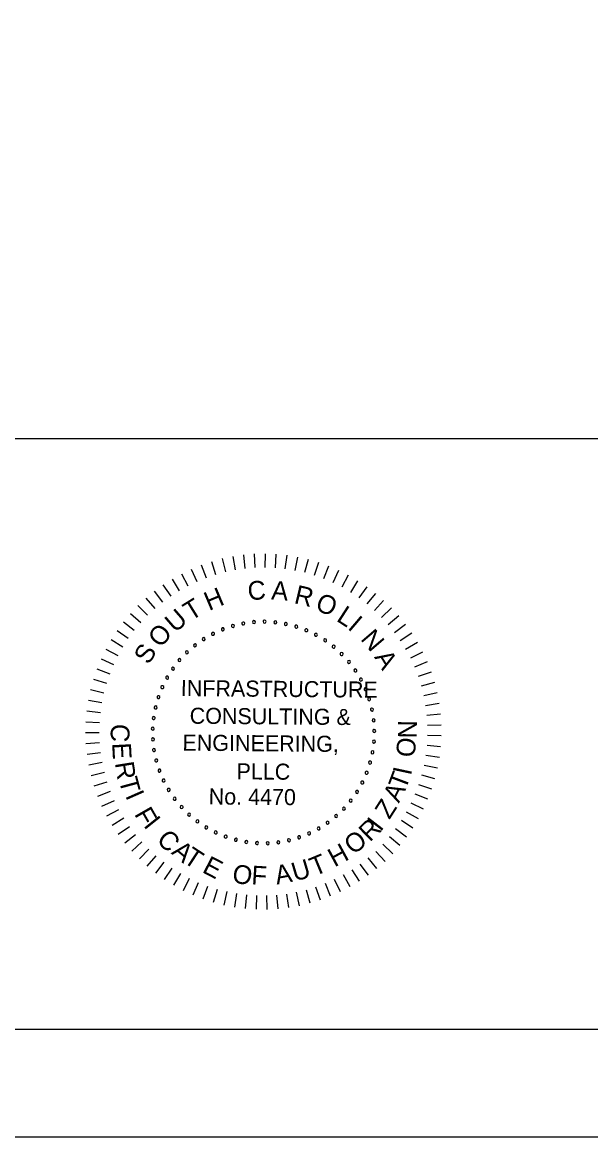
# Model space of a CAD drawing. Extents: x -121.2 to -24.9, y 6.4 to 66.6.
# Drawn here: x -53.93 to -46.88, y 6.35 to 20.18 of the extents above; entities that cross this region are included whole.
import ezdxf

# ---------------------------------------------------------------- set-up
doc = ezdxf.new("R2010")
doc.units = 0
for name, color, linetype in [('BR_BORDER LINES', 7, 'Continuous'), ('BR_TEXT', 7, 'Continuous'), ('Level 31', 7, 'Continuous')]:
    doc.layers.add(name, color=color, linetype=linetype)

msp = doc.modelspace()

# ---------------------------------------------------------------- linework, layer by layer
at = {"layer": 'BR_BORDER LINES'}
for p, q in [((-60.804, 15.017), (-46.496, 15.017)), ((-116.272, 7.683), (-26.496, 7.683))]:
    msp.add_line(p, q, dxfattribs=at)
at = {"layer": 'BR_TEXT'}
for p, q in [((-51.188, 13.572), (-51.169, 13.403)), ((-51.054, 13.583), (-51.045, 13.413)), ((-50.919, 13.586), (-50.921, 13.416)), ((-50.785, 13.58), (-50.796, 13.411)), ((-50.651, 13.567), (-50.673, 13.399)), ((-51.711, 13.447), (-51.651, 13.288)), ((-51.583, 13.49), (-51.533, 13.328)), ((-51.453, 13.526), (-51.413, 13.36)), ((-51.321, 13.553), (-51.292, 13.386)), ((-50.518, 13.545), (-50.55, 13.378)), ((-50.387, 13.515), (-50.429, 13.351)), ((-50.257, 13.478), (-50.31, 13.316)), ((-50.131, 13.432), (-50.193, 13.274)), ((-51.957, 13.338), (-51.878, 13.187)), ((-51.835, 13.396), (-51.766, 13.241)), ((-50.007, 13.379), (-50.079, 13.225)), ((-49.887, 13.318), (-49.968, 13.169)), ((-52.187, 13.2), (-52.091, 13.06)), ((-52.074, 13.272), (-51.987, 13.127)), ((-49.771, 13.251), (-49.86, 13.106)), ((-49.659, 13.176), (-49.757, 13.037)), ((-52.4, 13.034), (-52.287, 12.907)), ((-52.296, 13.12), (-52.192, 12.986)), ((-49.551, 13.094), (-49.658, 12.962)), ((-49.449, 13.006), (-49.564, 12.881)), ((-52.498, 12.942), (-52.378, 12.822)), ((-49.353, 12.913), (-49.475, 12.794)), ((-52.677, 12.741), (-52.543, 12.636)), ((-52.59, 12.844), (-52.463, 12.732)), ((-49.262, 12.813), (-49.391, 12.702)), ((-52.757, 12.633), (-52.617, 12.536)), ((-49.178, 12.708), (-49.313, 12.606)), ((-49.1, 12.598), (-49.242, 12.504)), ((-52.83, 12.52), (-52.684, 12.432)), ((-49.029, 12.484), (-49.176, 12.398)), ((-52.896, 12.402), (-52.745, 12.324)), ((-48.966, 12.365), (-49.117, 12.289)), ((-52.954, 12.281), (-52.799, 12.212)), ((-48.909, 12.243), (-49.065, 12.176)), ((-53.006, 12.157), (-52.847, 12.097)), ((-48.86, 12.117), (-49.02, 12.06)), ((-53.085, 11.9), (-52.92, 11.86)), ((-53.049, 12.029), (-52.887, 11.98)), ((-48.819, 11.989), (-48.982, 11.942)), ((-53.113, 11.768), (-52.946, 11.738)), ((-48.786, 11.859), (-48.951, 11.822)), ((-53.132, 11.635), (-52.964, 11.615)), ((-48.761, 11.727), (-48.928, 11.7)), ((-53.144, 11.501), (-52.974, 11.491)), ((-48.743, 11.593), (-48.912, 11.576)), ((-53.147, 11.366), (-52.978, 11.367)), ((-48.734, 11.459), (-48.904, 11.452)), ((-53.142, 11.231), (-52.973, 11.243)), ((-48.741, 11.19), (-48.91, 11.204)), ((-48.734, 11.324), (-48.903, 11.328)), ((-53.129, 11.097), (-52.961, 11.119)), ((-48.757, 11.056), (-48.925, 11.081)), ((-53.108, 10.965), (-52.941, 10.997)), ((-48.78, 10.923), (-48.947, 10.958)), ((-53.079, 10.833), (-52.914, 10.875)), ((-48.812, 10.793), (-48.976, 10.838)), ((-53.042, 10.704), (-52.88, 10.756)), ((-48.852, 10.664), (-49.013, 10.719)), ((-52.997, 10.577), (-52.838, 10.639)), ((-52.944, 10.453), (-52.79, 10.524)), ((-48.899, 10.538), (-49.056, 10.603)), ((-52.884, 10.333), (-52.734, 10.413)), ((-49.017, 10.296), (-49.165, 10.379)), ((-48.954, 10.415), (-49.107, 10.489)), ((-52.816, 10.216), (-52.672, 10.306)), ((-49.086, 10.181), (-49.229, 10.273)), ((-52.742, 10.104), (-52.603, 10.202)), ((-52.661, 9.996), (-52.529, 10.103)), ((-49.163, 10.07), (-49.3, 10.17)), ((-52.573, 9.894), (-52.448, 10.008)), ((-49.335, 9.863), (-49.459, 9.98)), ((-49.246, 9.964), (-49.376, 10.073)), ((-52.48, 9.797), (-52.362, 9.919)), ((-52.381, 9.706), (-52.27, 9.835)), ((-49.431, 9.768), (-49.547, 9.892)), ((-52.276, 9.622), (-52.173, 9.757)), ((-52.166, 9.543), (-52.072, 9.685)), ((-49.638, 9.597), (-49.738, 9.734)), ((-49.532, 9.679), (-49.64, 9.81)), ((-52.052, 9.472), (-51.967, 9.619)), ((-51.934, 9.408), (-51.858, 9.56)), ((-49.864, 9.451), (-49.947, 9.6)), ((-49.749, 9.521), (-49.841, 9.663)), ((-51.812, 9.351), (-51.745, 9.507)), ((-51.687, 9.302), (-51.629, 9.461)), ((-51.559, 9.26), (-51.511, 9.423)), ((-50.362, 9.249), (-50.407, 9.412)), ((-50.233, 9.288), (-50.288, 9.449)), ((-50.107, 9.335), (-50.171, 9.492)), ((-49.984, 9.389), (-50.058, 9.542)), ((-51.428, 9.226), (-51.391, 9.392)), ((-51.296, 9.2), (-51.269, 9.368)), ((-51.163, 9.183), (-51.146, 9.352)), ((-51.028, 9.173), (-51.022, 9.343)), ((-50.894, 9.172), (-50.898, 9.342)), ((-50.759, 9.179), (-50.773, 9.348)), ((-50.626, 9.194), (-50.65, 9.362)), ((-50.493, 9.217), (-50.528, 9.384))]:
    msp.add_line(p, q, dxfattribs=at)
for centre, start, end in [((-51.19, 12.72), 10.6038, 190.6038), ((-51.058, 12.738), 5.0653, 185.0653), ((-51.058, 12.738), 185.0653, 5.0653), ((-50.926, 12.743), 359.5268, 179.5268), ((-50.926, 12.743), 179.5268, 359.5268), ((-50.793, 12.735), 353.9884, 173.9884), ((-50.793, 12.735), 173.9884, 353.9884), ((-50.662, 12.714), 348.4499, 168.4499), ((-51.566, 12.592), 27.2191, 207.2191), ((-51.566, 12.592), 207.2191, 27.2191), ((-51.445, 12.647), 21.6807, 201.6807), ((-51.445, 12.647), 201.6807, 21.6807), ((-51.319, 12.689), 16.1422, 196.1422), ((-51.319, 12.689), 196.1422, 16.1422), ((-51.19, 12.72), 190.6038, 10.6038), ((-50.662, 12.714), 168.4499, 348.4499), ((-50.533, 12.681), 162.9114, 342.9114), ((-50.533, 12.681), 342.9114, 162.9114), ((-50.408, 12.636), 157.373, 337.373), ((-50.408, 12.636), 337.373, 157.373), ((-50.288, 12.579), 151.8345, 331.8345), ((-50.288, 12.579), 331.8345, 151.8345), ((-51.79, 12.449), 38.2961, 218.2961), ((-51.79, 12.449), 218.2961, 38.2961), ((-51.682, 12.526), 32.7576, 212.7576), ((-51.682, 12.526), 212.7576, 32.7576), ((-50.174, 12.51), 146.2961, 326.2961), ((-50.174, 12.51), 326.2961, 146.2961), ((-50.068, 12.431), 320.7576, 140.7576), ((-51.89, 12.362), 43.8345, 223.8345), ((-51.89, 12.362), 223.8345, 43.8345), ((-50.068, 12.431), 140.7576, 320.7576), ((-49.969, 12.342), 135.2191, 315.2191), ((-49.969, 12.342), 315.2191, 135.2191), ((-52.063, 12.16), 54.9114, 234.9114), ((-52.063, 12.16), 234.9114, 54.9114), ((-51.982, 12.265), 49.373, 229.373), ((-51.982, 12.265), 229.373, 49.373), ((-49.88, 12.244), 129.6807, 309.6807), ((-49.88, 12.244), 309.6807, 129.6807), ((-52.135, 12.048), 60.4499, 240.4499), ((-52.135, 12.048), 240.4499, 60.4499), ((-49.8, 12.137), 124.1422, 304.1422), ((-49.8, 12.137), 304.1422, 124.1422), ((-49.731, 12.024), 118.6038, 298.6038), ((-49.731, 12.024), 298.6038, 118.6038), ((-52.195, 11.93), 65.9884, 245.9884), ((-52.195, 11.93), 245.9884, 65.9884), ((-49.673, 11.904), 113.0653, 293.0653), ((-49.673, 11.904), 293.0653, 113.0653), ((-52.243, 11.806), 71.5268, 251.5268), ((-52.243, 11.806), 251.5268, 71.5268), ((-49.628, 11.779), 107.5268, 287.5268), ((-49.628, 11.779), 287.5268, 107.5268), ((-52.279, 11.678), 77.0653, 257.0653), ((-52.279, 11.678), 257.0653, 77.0653), ((-49.594, 11.651), 101.9884, 281.9884), ((-49.594, 11.651), 281.9884, 101.9884), ((-52.303, 11.547), 82.6038, 262.6038), ((-52.303, 11.547), 262.6038, 82.6038), ((-49.573, 11.519), 96.4499, 276.4499), ((-49.573, 11.519), 276.4499, 96.4499), ((-52.314, 11.415), 88.1422, 268.1422), ((-52.314, 11.415), 268.1422, 88.1422), ((-49.565, 11.387), 90.9114, 270.9114), ((-49.565, 11.387), 270.9114, 90.9114), ((-52.312, 11.282), 93.6807, 273.6807), ((-52.312, 11.282), 273.6807, 93.6807), ((-49.569, 11.254), 85.373, 265.373), ((-49.569, 11.254), 265.373, 85.373), ((-52.298, 11.15), 99.2191, 279.2191), ((-52.298, 11.15), 279.2191, 99.2191), ((-49.587, 11.122), 79.8345, 259.8345), ((-49.587, 11.122), 259.8345, 79.8345), ((-52.27, 11.02), 104.7576, 284.7576), ((-52.27, 11.02), 284.7576, 104.7576), ((-49.617, 10.993), 74.2961, 254.2961), ((-49.617, 10.993), 254.2961, 74.2961), ((-52.231, 10.893), 110.2961, 290.2961), ((-52.231, 10.893), 290.2961, 110.2961), ((-52.179, 10.771), 295.8345, 115.8345), ((-49.659, 10.867), 68.7576, 248.7576), ((-49.659, 10.867), 248.7576, 68.7576), ((-52.179, 10.771), 115.8345, 295.8345), ((-52.115, 10.654), 121.373, 301.373), ((-52.115, 10.654), 301.373, 121.373), ((-49.713, 10.746), 63.2191, 243.2191), ((-49.713, 10.746), 243.2191, 63.2191), ((-52.041, 10.544), 126.9114, 306.9114), ((-52.041, 10.544), 306.9114, 126.9114), ((-49.856, 10.522), 52.1422, 232.1422), ((-49.856, 10.522), 232.1422, 52.1422), ((-49.779, 10.63), 57.6807, 237.6807), ((-49.779, 10.63), 237.6807, 57.6807), ((-51.956, 10.441), 132.4499, 312.4499), ((-51.956, 10.441), 312.4499, 132.4499), ((-49.942, 10.421), 46.6038, 226.6038), ((-49.942, 10.421), 226.6038, 46.6038), ((-51.862, 10.348), 137.9884, 317.9884), ((-51.862, 10.348), 317.9884, 137.9884), ((-51.759, 10.263), 143.5268, 323.5268), ((-51.759, 10.263), 323.5268, 143.5268), ((-50.143, 10.247), 35.5268, 215.5268), ((-50.143, 10.247), 215.5268, 35.5268), ((-50.038, 10.329), 41.0653, 221.0653), ((-50.038, 10.329), 221.0653, 41.0653), ((-51.649, 10.189), 149.0653, 329.0653), ((-51.649, 10.189), 329.0653, 149.0653), ((-51.532, 10.126), 154.6038, 334.6038), ((-51.532, 10.126), 334.6038, 154.6038), ((-50.373, 10.115), 24.4499, 204.4499), ((-50.373, 10.115), 204.4499, 24.4499), ((-50.255, 10.175), 29.9884, 209.9884), ((-50.255, 10.175), 209.9884, 29.9884), ((-51.409, 10.075), 160.1422, 340.1422), ((-51.409, 10.075), 340.1422, 160.1422), ((-51.283, 10.036), 345.6807, 165.6807), ((-51.283, 10.036), 165.6807, 345.6807), ((-51.152, 10.009), 351.2191, 171.2191), ((-51.152, 10.009), 171.2191, 351.2191), ((-51.02, 9.995), 356.7576, 176.7576), ((-51.02, 9.995), 176.7576, 356.7576), ((-50.887, 9.993), 2.2961, 182.2961), ((-50.887, 9.993), 182.2961, 2.2961), ((-50.755, 10.005), 7.8345, 187.8345), ((-50.755, 10.005), 187.8345, 7.8345), ((-50.624, 10.029), 13.373, 193.373), ((-50.624, 10.029), 193.373, 13.373), ((-50.497, 10.066), 18.9114, 198.9114), ((-50.497, 10.066), 198.9114, 18.9114)]:
    msp.add_arc(centre, 0.0187, start, end, dxfattribs=at)
at = {"layer": 'Level 31'}
msp.add_lwpolyline([(-121.161, 6.35), (-25.161, 6.35), (-25.161, 65.017), (-121.161, 65.017)], close=True, dxfattribs=at)

# ---------------------------------------------------------------- texts
at = {"layer": 'BR_TEXT'}
for s, height, rotation, p in [('H', 0.233, 22.7882, (-51.615, 12.874)), ('C', 0.233, 4.7281, (-51.127, 13.006)), ('A', 0.233, 355.6981, (-50.848, 13.019)), ('R', 0.233, 346.6681, (-50.57, 12.974)), ('T', 0.233, 31.8182, (-51.841, 12.747)), ('O', 0.233, 337.638, (-50.31, 12.894)), ('U', 0.233, 40.8482, (-52.036, 12.597)), ('L', 0.233, 327.108, (-50.046, 12.759)), ('I', 0.233, 319.578, (-49.906, 12.659)), ('O', 0.233, 49.8782, (-52.215, 12.408)), ('N', 0.233, 310.548, (-49.744, 12.523)), ('S', 0.233, 58.9083, (-52.363, 12.199)), ('A', 0.233, 301.5179, (-49.57, 12.303)), ('INFRASTRUCTURE', 0.19939, 359.5268, (-51.966, 11.819)), ('CONSULTING &', 0.19939, 359.5268, (-51.856, 11.476)), ('N', 0.233, 89.2085, (-49.039, 11.293)), ('C', 0.233, 267.025, (-52.829, 11.479)), ('E', 0.233, 273.025, (-52.818, 11.235)), ('ENGINEERING,', 0.19939, 359.5268, (-51.946, 11.142)), ('O', 0.233, 83.2085, (-49.068, 11.05)), ('R', 0.233, 279.025, (-52.784, 10.989)), ('PLLC', 0.1994, 359.5268, (-51.275, 10.786)), ('I', 0.233, 77.9093, (-49.11, 10.825)), ('T', 0.233, 285.025, (-52.737, 10.779)), ('T', 0.233, 69.3954, (-49.178, 10.645)), ('I', 0.233, 293.7713, (-52.658, 10.584)), ('No. 4470', 0.1994, 359.5268, (-51.62, 10.474)), ('A', 0.233, 63.3954, (-49.26, 10.484)), ('Z', 0.233, 57.3954, (-49.377, 10.28)), ('F', 0.233, 299.7713, (-52.548, 10.355)), ('I', 0.233, 308.5268, (-52.436, 10.211)), ('R', 0.233, 44.5268, (-49.619, 10)), ('I', 0.233, 52.3339, (-49.487, 10.127)), ('C', 0.233, 314.5268, (-52.278, 10.024)), ('O', 0.233, 38.5268, (-49.823, 9.841)), ('A', 0.233, 320.5268, (-52.093, 9.868)), ('H', 0.233, 28.5268, (-50.058, 9.691)), ('T', 0.233, 326.5268, (-51.948, 9.765)), ('E', 0.233, 332.5268, (-51.712, 9.638)), ('T', 0.233, 22.5268, (-50.306, 9.58)), ('O', 0.233, 350.5268, (-51.338, 9.508)), ('F', 0.233, 356.5268, (-51.094, 9.483)), ('A', 0.233, 10.5268, (-50.775, 9.479)), ('U', 0.233, 16.5268, (-50.551, 9.515))]:
    msp.add_text(s, height=height, rotation=rotation, dxfattribs=at).set_placement(p)

doc.saveas('drawing.dxf')
